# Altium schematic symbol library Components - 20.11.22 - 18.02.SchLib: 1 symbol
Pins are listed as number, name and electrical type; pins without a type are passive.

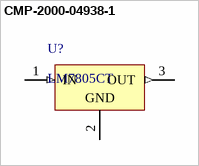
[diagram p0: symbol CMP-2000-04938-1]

## CMP-2000-04938-1
designator U?, comment LM7805CT
Positive Voltage Regulator, 5 V, 1 A, -40 to 125 degC, 3-Pin TO-220, RoHS, Tube; Manufacturer: FairchildSemiconductor; Maximum Input Voltage: 35V; Maximum Quiescent Current: 8mA; Load Regulation: 100mV; Maximum Output Current: 2.2(Typ)A; Output Type: Fixed; Typical Dropout Voltage @ Current: 2@1AV; Rad Hard: No; Output Voltage: 5V; Accuracy: ±4%; Number of Outputs: 1
footprint FAIR-TO-220-3 (FM, 3-Leads, Body 10.2x4.7mm, Pitch 2.54mm)
pins: 1 IN (in), 2 GND (power), 3 OUT (out)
